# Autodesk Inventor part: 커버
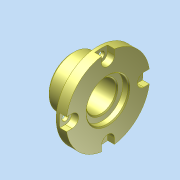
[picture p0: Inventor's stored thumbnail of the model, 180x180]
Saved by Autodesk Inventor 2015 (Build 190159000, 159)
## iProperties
Created: 2026-09
Part Number: 커버
Material: 일반
Document SubType Name: Modeling
Designer: SCD-A06
Density: 1 g/cm^3
Appearance: 기본값
Author: SCD-A06
Author: jhkim
Creation Date: 2026-08-27
Sending System: Autodesk Inventor 2027
Preprocessor: ST-DEVELOPER v20.1
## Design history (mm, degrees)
node "커버1"
node "솔리드1"
node "기준1"
